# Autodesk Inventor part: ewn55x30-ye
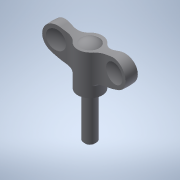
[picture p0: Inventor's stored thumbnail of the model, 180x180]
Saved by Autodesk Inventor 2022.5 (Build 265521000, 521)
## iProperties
Created: 2016-12
Part Number: ewn55x30-ye
Material: 一般
Document SubType Name: Modeling
Designer: imaocorp
Density: 1 g/cm^3
Appearance: 既定
Author: imaocorp
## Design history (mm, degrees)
node "ewn55x30-ye.x_t1"
node "ewn55x30-ye"
node "Base1"
